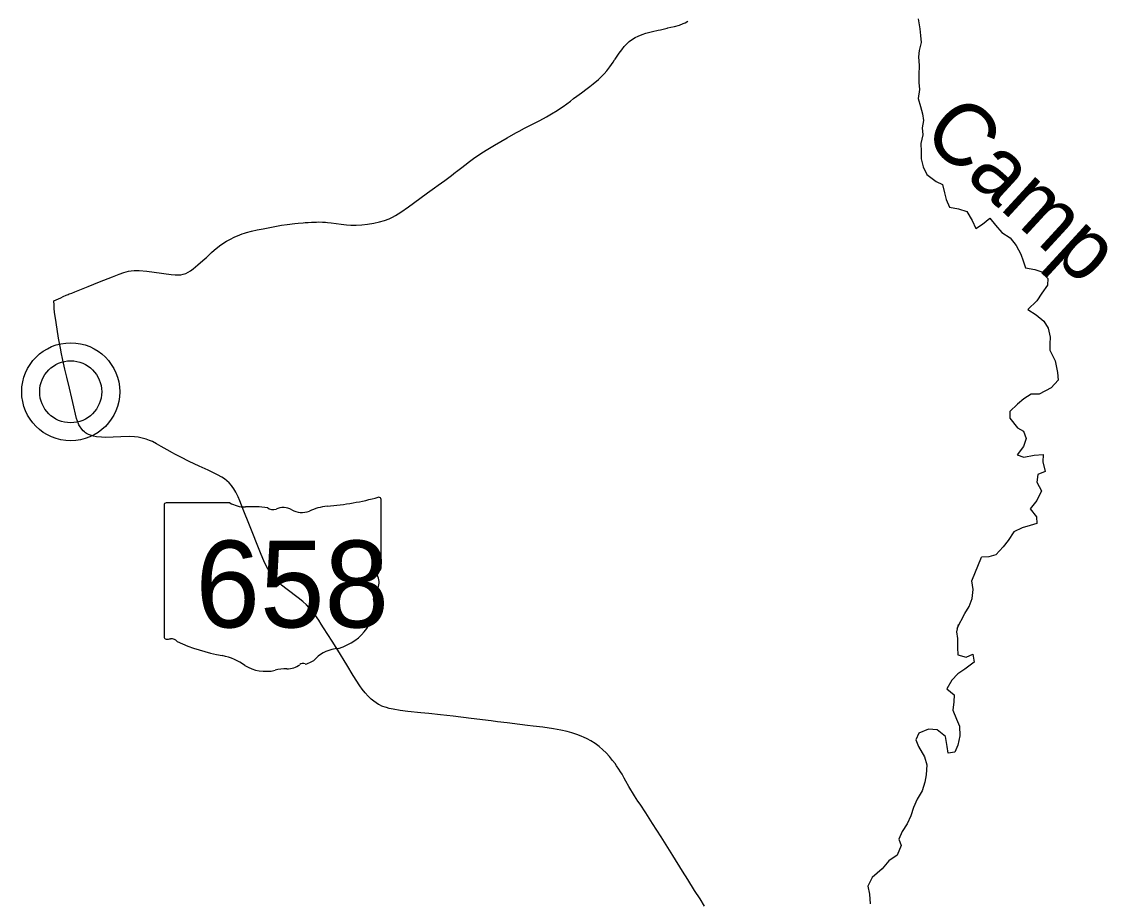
# Model space of a CAD drawing. Extents: x -12.1 to 34, y 0 to 22.
# Drawn here: x 3.693 to 5.242, y 16.204 to 17.456 of the extents above; entities that cross this region are included whole.
import ezdxf

# ---------------------------------------------------------------- set-up
doc = ezdxf.new("R2010")
doc.units = 0
for name, color, linetype in [('GM_X_Minor_River', 7, 'Continuous'), ('GM_X_Minor_River_Text', 7, 'Continuous'), ('GM_X_State_Route', 7, 'Continuous'), ('GM_X_State_Shield', 7, 'Continuous'), ('GM_X_Unincorporated', 7, 'Continuous'), ('GM_X_Unincorporated_Location', 7, 'Continuous')]:
    doc.layers.add(name, color=color, linetype=linetype)

msp = doc.modelspace()

# ---------------------------------------------------------------- linework, layer by layer
at = {"layer": 'GM_X_Minor_River'}
for points in [[(4.9706, 17.4596), (4.9732, 17.4454), (4.9743, 17.4362), (4.9751, 17.4259), (4.9721, 17.4148), (4.9711, 17.4059), (4.9723, 17.3935), (4.9717, 17.38), (4.9718, 17.369), (4.9726, 17.3594), (4.9709, 17.3462), (4.9742, 17.3349), (4.9768, 17.3243), (4.9783, 17.315), (4.9767, 17.3044), (4.9775, 17.2948), (4.9747, 17.2823), (4.9752, 17.2709), (4.9749, 17.2603), (4.9779, 17.2489), (4.983, 17.238), (4.9962, 17.2281), (5.0054, 17.224)], [(5.0054, 17.224), (5.0084, 17.2119), (5.0109, 17.2023), (5.0156, 17.1917), (5.0284, 17.189), (5.0401, 17.1852), (5.0477, 17.1728), (5.0531, 17.1612), (5.0626, 17.1673), (5.0728, 17.1759), (5.0811, 17.1657), (5.09, 17.1555), (5.1021, 17.1481), (5.1104, 17.1369), (5.1169, 17.1245), (5.1205, 17.1149), (5.1238, 17.105), (5.137, 17.1026), (5.1469, 17.0995), (5.1555, 17.09), (5.1552, 17.0804), (5.1468, 17.069), (5.1399, 17.0582), (5.1272, 17.0457), (5.139, 17.038), (5.1497, 17.0292), (5.1562, 17.019), (5.1588, 17.0065), (5.1585, 16.9969), (5.1586, 16.9877), (5.1658, 16.9725), (5.1692, 16.9562), (5.1703, 16.9452), (5.1602, 16.9341), (5.1433, 16.9254), (5.1316, 16.9253), (5.1214, 16.9184), (5.1122, 16.9112), (5.1013, 16.9004), (5.1014, 16.8908), (5.1122, 16.8771), (5.1211, 16.8726), (5.1247, 16.8619), (5.1209, 16.8509), (5.1118, 16.8387), (5.1214, 16.8356), (5.1359, 16.8382), (5.1487, 16.8391), (5.1484, 16.8288), (5.1518, 16.8149), (5.1415, 16.8109), (5.1398, 16.7999), (5.1467, 16.7875), (5.1401, 16.7739), (5.1303, 16.7621), (5.1393, 16.7505), (5.1397, 16.7409), (5.1305, 16.738), (5.1189, 16.735), (5.1072, 16.7292), (5.0988, 16.717), (5.0918, 16.7077), (5.0813, 16.6963), (5.0714, 16.6937), (5.0612, 16.6932)], [(5.0265, 16.5918), (5.0375, 16.6127), (5.0434, 16.6227), (5.0475, 16.6344), (5.0492, 16.6469), (5.0473, 16.6593), (5.0612, 16.6932)], [(5.0276, 16.5971), (5.0255, 16.5865), (5.0267, 16.5772), (5.0268, 16.5644), (5.0272, 16.5541), (5.0393, 16.5504), (5.0489, 16.5551), (5.0508, 16.5437), (5.0374, 16.5336), (5.0271, 16.5268), (5.0187, 16.5178), (5.0117, 16.5057), (5.0221, 16.4969), (5.0215, 16.4869), (5.0202, 16.4752), (5.0256, 16.4621), (5.0296, 16.4522), (5.0301, 16.4387), (5.0274, 16.4252), (5.0232, 16.4155), (5.0136, 16.414), (5.0121, 16.4233), (5.0095, 16.4374), (4.9977, 16.4469), (4.9853, 16.4479), (4.9715, 16.4424), (4.9673, 16.4328), (4.9713, 16.4232), (4.9796, 16.4087), (4.9829, 16.3974), (4.982, 16.3832), (4.9803, 16.3725), (4.9765, 16.3604), (4.9692, 16.3482), (4.9643, 16.3365), (4.9605, 16.3247), (4.955, 16.3133), (4.948, 16.3025), (4.9431, 16.2915), (4.9464, 16.2823), (4.9408, 16.2684), (4.9292, 16.2604), (4.9197, 16.2493), (4.9053, 16.2368), (4.899, 16.2246), (4.9012, 16.2129), (4.9024, 16.1994)]]:
    msp.add_lwpolyline(points, dxfattribs=at)
at = {"layer": 'GM_X_State_Route'}
msp.add_lwpolyline([(4.6662, 16.1961), (4.6599, 16.2062), (4.6522, 16.2181), (4.6424, 16.2338), (4.635, 16.2456), (4.621, 16.2682), (4.6045, 16.2946), (4.5924, 16.3139), (4.5876, 16.3212), (4.5851, 16.3251), (4.5825, 16.3291), (4.5744, 16.3412), (4.5715, 16.3455), (4.5667, 16.3529), (4.5583, 16.3665), (4.5543, 16.374), (4.5519, 16.3783), (4.5488, 16.3839), (4.5465, 16.3875), (4.5441, 16.3913), (4.5411, 16.3958), (4.5388, 16.399), (4.5353, 16.4035), (4.5309, 16.4089), (4.526, 16.4144), (4.5214, 16.4188), (4.516, 16.4234), (4.5104, 16.4275), (4.5042, 16.4314), (4.499, 16.4342), (4.4939, 16.4366), (4.4913, 16.4378), (4.4856, 16.44), (4.48, 16.4419), (4.4773, 16.4428), (4.4707, 16.4445), (4.4615, 16.4466), (4.451, 16.4485), (4.4361, 16.4509), (4.4223, 16.4525), (4.4142, 16.4535), (4.4031, 16.4549), (4.3852, 16.457), (4.3713, 16.4586), (4.3621, 16.4597), (4.3337, 16.4634), (4.3083, 16.4664), (4.2899, 16.4685), (4.2734, 16.4703), (4.262, 16.4714), (4.2435, 16.4733), (4.2325, 16.4748), (4.2227, 16.4764), (4.217, 16.4777), (4.2131, 16.4787), (4.2114, 16.4792), (4.208, 16.4804), (4.2066, 16.481), (4.2032, 16.4826), (4.2019, 16.4833), (4.1982, 16.4854), (4.195, 16.4879), (4.1913, 16.4909), (4.1868, 16.4952), (4.1829, 16.4996), (4.1785, 16.5052), (4.1752, 16.51), (4.1657, 16.5247), (4.1564, 16.5395), (4.1437, 16.5604), (4.1356, 16.5732), (4.1235, 16.5924), (4.12, 16.5978), (4.1165, 16.6031), (4.1108, 16.6112), (4.1059, 16.6176), (4.1025, 16.6215), (4.0989, 16.6252), (4.0937, 16.6299), (4.0873, 16.6351), (4.0717, 16.6469), (4.0637, 16.6533), (4.0587, 16.6579), (4.0545, 16.662), (4.051, 16.666), (4.0487, 16.6692), (4.0479, 16.6703), (4.0471, 16.6715), (4.0451, 16.6745), (4.0439, 16.6765), (4.0415, 16.6809), (4.0383, 16.688), (4.0346, 16.697), (4.0171, 16.7408), (4.0099, 16.7586), (4.0041, 16.7732), (4.0016, 16.779), (4.0004, 16.7817), (3.9983, 16.7858), (3.9957, 16.7902), (3.9934, 16.7935), (3.9921, 16.7952), (3.9889, 16.7988), (3.9855, 16.8019), (3.9823, 16.8044), (3.9783, 16.807), (3.9724, 16.8103), (3.9589, 16.8169), (3.9462, 16.8227), (3.932, 16.8295), (3.9199, 16.8354), (3.9117, 16.8397), (3.9081, 16.8417), (3.9004, 16.8459), (3.8918, 16.8509), (3.8853, 16.8547), (3.8798, 16.8576), (3.8755, 16.8594), (3.8708, 16.8612), (3.8651, 16.8627), (3.8594, 16.8638), (3.8539, 16.8644), (3.8473, 16.8647), (3.8346, 16.8646), (3.8235, 16.864), (3.8134, 16.8637), (3.8071, 16.8638), (3.7997, 16.8646), (3.7955, 16.8655), (3.7926, 16.8663), (3.7887, 16.8679), (3.7858, 16.8694), (3.7842, 16.8703), (3.7826, 16.8716), (3.7809, 16.873), (3.7789, 16.8752), (3.7778, 16.8767), (3.7765, 16.8786), (3.7749, 16.8813), (3.7737, 16.8843), (3.7728, 16.8866), (3.7716, 16.8904), (3.77, 16.8966), (3.7677, 16.9071), (3.7649, 16.9195), (3.7615, 16.9337), (3.7578, 16.9492), (3.7559, 16.9571), (3.7549, 16.961), (3.752, 16.9737), (3.7496, 16.9851), (3.7489, 16.9885), (3.7458, 17.0051), (3.7422, 17.0271), (3.7409, 17.0363), (3.7402, 17.0416), (3.7397, 17.0477), (3.7394, 17.0519), (3.739, 17.058), (3.749, 17.0625), (3.7524, 17.0642), (3.7566, 17.0662), (3.7593, 17.0673), (3.7609, 17.0679), (3.7648, 17.0692), (3.769, 17.0711), (3.7879, 17.0787), (3.8042, 17.085), (3.8225, 17.0925), (3.8323, 17.0963), (3.839, 17.0985), (3.8453, 17.1002), (3.8493, 17.1009), (3.8535, 17.1013), (3.8605, 17.1013), (3.8716, 17.1003), (3.882, 17.0991), (3.9062, 17.0957), (3.9119, 17.0952), (3.9159, 17.0952), (3.9199, 17.0954), (3.9232, 17.0961), (3.927, 17.0973), (3.9306, 17.0989), (3.934, 17.1009), (3.9377, 17.1036), (3.9444, 17.1092), (3.9547, 17.1186), (3.9564, 17.1201), (3.9603, 17.1237), (3.9637, 17.1269), (3.9677, 17.1303), (3.9753, 17.1366), (3.9801, 17.14), (3.9851, 17.1431), (3.9908, 17.1462), (3.996, 17.1488), (4.0041, 17.1523), (4.0074, 17.1535), (4.0107, 17.1547), (4.0135, 17.1555), (4.0209, 17.1574), (4.0288, 17.1591), (4.0374, 17.1609), (4.0494, 17.1633), (4.0565, 17.1645), (4.0637, 17.1657), (4.0718, 17.1668), (4.0827, 17.1681), (4.0873, 17.1686), (4.0942, 17.1694), (4.0971, 17.1697), (4.1017, 17.1699), (4.1064, 17.1702), (4.1134, 17.1704), (4.1168, 17.1706), (4.1221, 17.1704), (4.1262, 17.1701), (4.1291, 17.1698), (4.1342, 17.1691), (4.1412, 17.1682), (4.1486, 17.1673), (4.1561, 17.1665), (4.1625, 17.1661), (4.17, 17.166), (4.1781, 17.1665), (4.1861, 17.1674), (4.1953, 17.1688), (4.2032, 17.1705), (4.2105, 17.1725), (4.2169, 17.1749), (4.2215, 17.1772), (4.2261, 17.1798), (4.2334, 17.1844), (4.2443, 17.1921), (4.2608, 17.2041), (4.2717, 17.2119), (4.2817, 17.219), (4.2868, 17.2227), (4.2963, 17.2296), (4.3056, 17.2366), (4.3116, 17.2412), (4.3129, 17.2422), (4.3184, 17.2465), (4.3267, 17.253), (4.3294, 17.2551), (4.3392, 17.2625), (4.344, 17.2658), (4.3489, 17.269), (4.3573, 17.2741), (4.3669, 17.2797), (4.3849, 17.2902), (4.3975, 17.2975), (4.402, 17.3), (4.4097, 17.3041), (4.4181, 17.3083), (4.4315, 17.3152), (4.4413, 17.3204), (4.4484, 17.3243), (4.4562, 17.3293), (4.4582, 17.3306), (4.4649, 17.335), (4.47, 17.3388), (4.4752, 17.3426), (4.4797, 17.3462), (4.4845, 17.3496), (4.491, 17.3545), (4.4989, 17.3604), (4.5031, 17.3635), (4.5077, 17.3671), (4.5152, 17.3734), (4.5178, 17.3757), (4.5234, 17.3816), (4.5272, 17.3859), (4.5313, 17.3915), (4.536, 17.3981), (4.5382, 17.4015), (4.5388, 17.4025), (4.5448, 17.4111), (4.5483, 17.4158), (4.552, 17.4204), (4.5561, 17.4246), (4.5591, 17.4274), (4.5638, 17.431), (4.5674, 17.4331), (4.5716, 17.4352), (4.5776, 17.4376), (4.5827, 17.4392), (4.5923, 17.4417), (4.6003, 17.4436), (4.6037, 17.4443), (4.6133, 17.4467), (4.6139, 17.4468), (4.6183, 17.4479), (4.6234, 17.4491), (4.6307, 17.451), (4.6361, 17.453), (4.6387, 17.4542), (4.6426, 17.4564)], dxfattribs=at)
at = {"layer": 'GM_X_State_Shield'}
for p, q in [((3.9898, 16.7706), (3.8993, 16.7706)), ((4.2053, 16.6771), (4.2053, 16.7752)), ((3.8963, 16.7673), (3.8963, 16.5797)), ((4.2053, 16.6771), (4.2053, 16.6771))]:
    msp.add_line(p, q, dxfattribs=at)
for centre, major_axis, start_param, end_param in [((3.8998, 16.7677), (0.00358, 0), 1.712693, 3.28349), ((4.0114, 16.7924), (0.0347, 0), 4.042523, 4.731795), ((4.0952, 17.0264), (0.3277, 0), 4.814394, 5.042369), ((4.2019, 16.7756), (0.00344, 0), 6.141152, 7.989035), ((4.0229, 16.6652), (0.1246, 0), 1.404758, 1.657858), ((4.0512, 16.7687), (0.01, 0), 3.836095, 5.185415), ((4.0659, 16.747), (0.0208, 0), 0.950623, 2.079405), ((4.0928, 16.7768), (0.0251, 0), 4.081561, 5.145723), ((4.137, 16.7133), (0.0659, 0), 1.699011, 2.107814), ((4.2016, 16.6767), (0.00368, 0), 5.05454, 6.418171), ((4.2045, 16.6699), (0.00532, 0), 1.883978, 3.671073), ((4.1706, 16.6575), (0.032, 0), 5.934695, 6.695948), ((4.2176, 16.636), (0.0232, 0), 2.387724, 3.262537), ((4.1136, 16.6235), (0.082, 0), 5.101752, 6.440018), ((3.8999, 16.5793), (0.00361, 0), 3.00124, 4.508301), ((3.9004, 16.5985), (0.0276, 0), 4.665946, 4.897461), ((3.9061, 16.5689), (0.00994, 0), 0.519207, 1.627899), ((4.0315, 16.7375), (0.2366, 0), 4.195997, 4.488961), ((3.961, 16.4954), (0.074, 0), 0.823519, 1.323587), ((4.1481, 16.5271), (0.0449, 0), 1.647645, 2.488434), ((4.0411, 16.568), (0.047, 0), 4.026481, 4.996735), ((4.0716, 16.5539), (0.025, 0), 4.691044, 5.507374), ((4.0943, 16.5358), (0.00705, 0), 1.147584, 2.315152), ((4.0913, 16.5615), (0.0265, 0), 4.937069, 5.64225), ((4.0682, 16.5031), (0.0386, 0), 1.495662, 1.94098)]:
    msp.add_ellipse(centre, major_axis=major_axis, ratio=0.8, start_param=start_param, end_param=end_param, dxfattribs=at)
at = {"layer": 'GM_X_Unincorporated'}
for radius in [0.0698, 0.0442]:
    msp.add_circle((3.7631, 16.9286), radius, dxfattribs=at)
at = {"layer": 'GM_X_Unincorporated_Location'}
msp.add_line((3.7631, 16.9286), (3.7631, 16.9286), dxfattribs=at)

# ---------------------------------------------------------------- texts
at = {"layer": 'GM_X_Minor_River_Text'}
msp.add_text('Camp', height=0.08877, rotation=317.3793, dxfattribs=at).set_placement((4.9738, 17.2926))
at = {"layer": 'GM_X_State_Shield'}
msp.add_text('658', height=0.1236, dxfattribs=at).set_placement((3.9409, 16.593))

doc.saveas('drawing.dxf')
